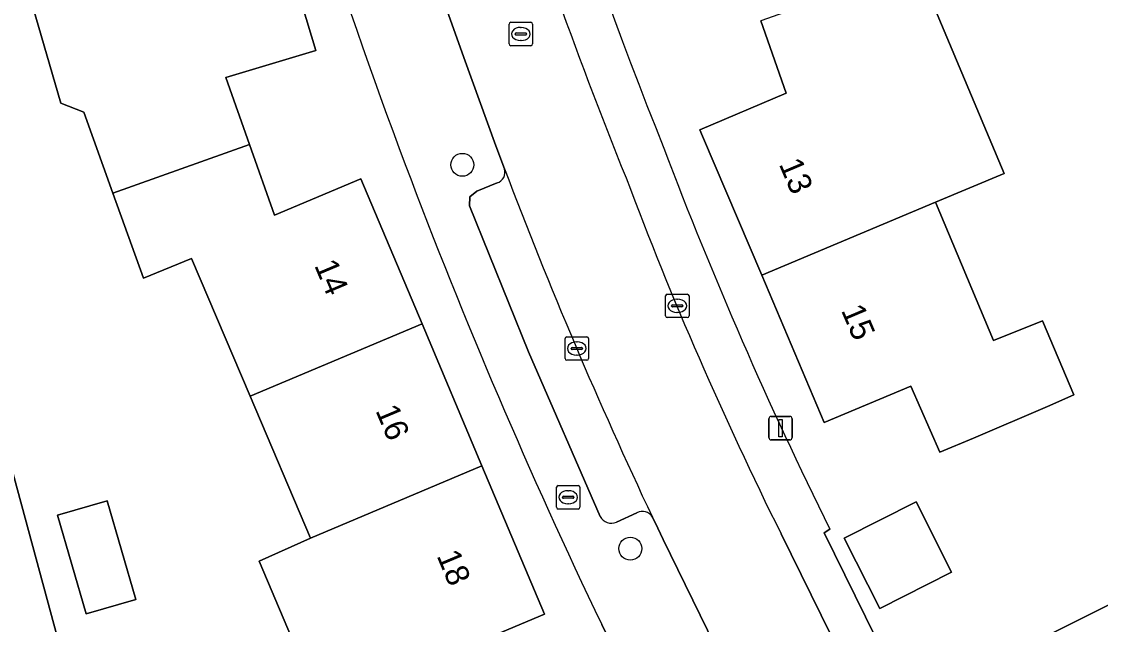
# Model space of a CAD drawing. Extents: x 159053 to 160042, y 380449 to 381423.
# Drawn here: x 159407.8 to 159453.83, y 380893.4 to 380919.13 of the extents above; entities that cross this region are included whole.
import ezdxf

# ---------------------------------------------------------------- set-up
doc = ezdxf.new("R2010")
doc.units = 0
for name, color, linetype in [('IMGEO_Boom', 7, 'Continuous'), ('IMGEO_Brandkraan', 7, 'Continuous'), ('IMGEO_Erf', 7, 'Continuous'), ('IMGEO_Groenvoorziening', 7, 'Continuous'), ('IMGEO_Kolk', 7, 'Continuous'), ('IMGEO_Lichtmast', 7, 'Continuous'), ('IMGEO_Pand', 7, 'Continuous'), ('IMGEO_Pand_nummerreeks', 7, 'Continuous'), ('IMGEO_Parkeervlak_open', 7, 'Continuous'), ('IMGEO_Rijbaan_lokaal_open', 7, 'Continuous'), ('IMGEO_Rioolput', 7, 'Continuous'), ('IMGEO_Voetpad_open', 7, 'Continuous')]:
    doc.layers.add(name, color=color, linetype=linetype)

msp = doc.modelspace()

# ---------------------------------------------------------------- linework, layer by layer
at = {"layer": 'IMGEO_Boom'}
for centre in [(159426.603, 380913.013), (159433.772, 380896.633)]:
    msp.add_circle(centre, 0.489, dxfattribs=at)
at = {"layer": 'IMGEO_Brandkraan'}
for p, q in [((159430.62, 380898.397), (159430.62, 380899.249)), ((159430.695, 380899.323), (159431.547, 380899.323)), ((159431.621, 380899.249), (159431.621, 380898.397)), ((159430.879, 380898.817), (159430.879, 380898.829)), ((159431.317, 380898.78), (159430.919, 380898.78)), ((159430.922, 380898.866), (159431.32, 380898.866)), ((159431.108, 380899.103), (159431.133, 380899.103)), ((159431.363, 380898.829), (159431.363, 380898.817)), ((159431.547, 380898.323), (159430.695, 380898.323)), ((159431.131, 380898.543), (159431.106, 380898.543))]:
    msp.add_line(p, q, dxfattribs=at)
for points in [[(159430.62, 380898.397), (159430.62, 380899.249)], [(159430.695, 380899.323), (159431.547, 380899.323)], [(159431.621, 380899.249), (159431.621, 380898.397)], [(159431.547, 380898.323), (159430.695, 380898.323)]]:
    msp.add_lwpolyline(points, dxfattribs=at)
for centre, radius, start, end in [((159430.697, 380899.247), 0.0765, 91.552, 178.448), ((159430.697, 380899.247), 0.0765, 91.552, 178.448), ((159431.545, 380899.247), 0.0765, 1.552, 88.448), ((159431.545, 380899.247), 0.0765, 1.552, 88.448), ((159430.919, 380898.826), 0.0403, 85.8775, 175.7526), ((159430.916, 380898.816), 0.0366, 178.938, 274.7102), ((159431.32, 380898.823), 0.043, 264.8664, 352.4533), ((159431.324, 380898.828), 0.0386, 1.7309, 96.639), ((159430.697, 380898.399), 0.0765, 181.552, 268.448), ((159430.697, 380898.399), 0.0765, 181.552, 268.448), ((159431.545, 380898.399), 0.0765, 271.552, 358.448), ((159431.545, 380898.399), 0.0765, 271.552, 358.448)]:
    msp.add_arc(centre, radius, start, end, dxfattribs=at)
for centre, major_axis, ratio, start_param, end_param in [((159431.107, 380898.823), (-0.387, 0.002), 0.722429, 4.712389, 7.853982), ((159431.132, 380898.823), (-0.39, 0.002), 0.717154, 1.570796, 4.712389)]:
    msp.add_ellipse(centre, major_axis=major_axis, ratio=ratio, start_param=start_param, end_param=end_param, dxfattribs=at)
at = {"layer": 'IMGEO_Erf'}
for points in [[(159408.965, 380964.525), (159406.59, 380964.068), (159401.237, 380962.888), (159388.835, 380959.508), (159387.783, 380959.221), (159399.303, 380929.877), (159412.172, 380882.306), (159415.898, 380867.448), (159416.608, 380864.597), (159416.656, 380864.403), (159417.452, 380863.784), (159418.791, 380864.086), (159429.053, 380866.431)], [(159418.369, 380924.458), (159420.347, 380917.887), (159416.517, 380916.735), (159417.526, 380913.88), (159418.591, 380910.865), (159422.277, 380912.418), (159424.886, 380906.225), (159427.441, 380900.163), (159430.109, 380893.831), (159426.433, 380892.288), (159427.633, 380889.421), (159427.088, 380889.202), (159422.993, 380887.56), (159421.762, 380887.066), (159417.932, 380896.096), (159420.125, 380897.081), (159417.551, 380903.138), (159415.055, 380909.013), (159413.002, 380908.175), (159411.697, 380911.8), (159410.451, 380915.26), (159409.474, 380915.644), (159407.916, 380920.993)], [(159445.993, 380921.527), (159449.718, 380912.643), (159446.793, 380911.415), (159449.265, 380905.517), (159451.363, 380906.349), (159452.697, 380903.191), (159451.578, 380902.697), (159448.411, 380901.353), (159446.975, 380900.743), (159445.736, 380903.567), (159442.047, 380902.022), (159439.379, 380908.299), (159436.855, 380914.238), (159436.742, 380914.504), (159440.424, 380916.069), (159439.335, 380919.157)], [(159452.048, 380890.082), (159450.799, 380892.535), (159457.704, 380896), (159468.395, 380899.243), (159469.193, 380896.611), (159480.383, 380897.975), (159480.699, 380888.61)], [(159442.282, 380897.463), (159442.043, 380897.312), (159451.283, 380878.508)], [(159442.437, 380873.196), (159432.55, 380893.397)]]:
    msp.add_lwpolyline(points, dxfattribs=at)
for points in [[(159411.451, 380898.672), (159412.675, 380894.468), (159410.558, 380893.852), (159409.334, 380898.055)], [(159447.479, 380895.625), (159444.416, 380894.078), (159442.9, 380897.079), (159445.963, 380898.626)]]:
    msp.add_lwpolyline(points, close=True, dxfattribs=at)
for centre, radius, start, end in [((159643.326, 380995.404), 234.129, 188.67315, 200.59863), ((159624.348, 380989.377), 203.718, 192.99702, 201.80088), ((159607.884, 380979.275), 184.709, 200.78794, 206.29061), ((159654.06, 380999.595), 245.652, 200.63276, 205.61432)]:
    msp.add_arc(centre, radius, start, end, dxfattribs=at)
at = {"layer": 'IMGEO_Groenvoorziening'}
msp.add_lwpolyline([(159339.63, 380858.444), (159343.386, 380845.223), (159357.481, 380849.075), (159416.608, 380864.597), (159415.898, 380867.448), (159412.172, 380882.306), (159399.303, 380929.877)], dxfattribs=at)
at = {"layer": 'IMGEO_Kolk'}
for p, q in [((159435.349, 380907.493), (159436.201, 380907.493)), ((159435.274, 380906.567), (159435.274, 380907.419)), ((159435.533, 380906.987), (159435.533, 380906.999)), ((159435.576, 380907.036), (159435.974, 380907.036)), ((159435.762, 380907.273), (159435.787, 380907.273)), ((159436.017, 380906.999), (159436.017, 380906.987)), ((159436.275, 380907.419), (159436.275, 380906.567)), ((159435.971, 380906.95), (159435.573, 380906.95)), ((159435.785, 380906.713), (159435.76, 380906.713)), ((159436.201, 380906.493), (159435.349, 380906.493)), ((159431.063, 380905.672), (159431.915, 380905.672)), ((159430.988, 380904.746), (159430.988, 380905.598)), ((159431.247, 380905.166), (159431.247, 380905.178)), ((159431.29, 380905.215), (159431.688, 380905.215)), ((159431.476, 380905.452), (159431.501, 380905.452)), ((159431.731, 380905.178), (159431.731, 380905.166)), ((159431.989, 380905.598), (159431.989, 380904.746)), ((159431.685, 380905.129), (159431.287, 380905.129)), ((159431.499, 380904.892), (159431.474, 380904.892)), ((159431.915, 380904.672), (159431.063, 380904.672))]:
    msp.add_line(p, q, dxfattribs=at)
for points in [[(159435.349, 380907.493), (159436.201, 380907.493)], [(159435.274, 380906.567), (159435.274, 380907.419)], [(159436.275, 380907.419), (159436.275, 380906.567)], [(159436.201, 380906.493), (159435.349, 380906.493)], [(159431.063, 380905.672), (159431.915, 380905.672)], [(159430.988, 380904.746), (159430.988, 380905.598)], [(159431.989, 380905.598), (159431.989, 380904.746)], [(159431.915, 380904.672), (159431.063, 380904.672)]]:
    msp.add_lwpolyline(points, dxfattribs=at)
for centre, radius, start, end in [((159435.351, 380907.417), 0.0765, 91.552, 178.448), ((159435.351, 380907.417), 0.0765, 91.552, 178.448), ((159436.199, 380907.417), 0.0765, 1.552, 88.448), ((159436.199, 380907.417), 0.0765, 1.552, 88.448), ((159435.573, 380906.996), 0.0403, 85.8775, 175.7526), ((159435.57, 380906.986), 0.0366, 178.938, 274.7102), ((159435.974, 380906.993), 0.043, 264.8664, 352.4533), ((159435.978, 380906.998), 0.0386, 1.7309, 96.639), ((159435.351, 380906.569), 0.0765, 181.552, 268.448), ((159435.351, 380906.569), 0.0765, 181.552, 268.448), ((159436.199, 380906.569), 0.0765, 271.552, 358.448), ((159436.199, 380906.569), 0.0765, 271.552, 358.448), ((159431.065, 380905.596), 0.0765, 91.552, 178.448), ((159431.065, 380905.596), 0.0765, 91.552, 178.448), ((159431.913, 380905.596), 0.0765, 1.552, 88.448), ((159431.913, 380905.596), 0.0765, 1.552, 88.448), ((159431.287, 380905.175), 0.0403, 85.8775, 175.7526), ((159431.284, 380905.165), 0.0366, 178.938, 274.7102), ((159431.688, 380905.172), 0.043, 264.8664, 352.4533), ((159431.692, 380905.177), 0.0386, 1.7309, 96.639), ((159431.065, 380904.748), 0.0765, 181.552, 268.448), ((159431.065, 380904.748), 0.0765, 181.552, 268.448), ((159431.913, 380904.748), 0.0765, 271.552, 358.448), ((159431.913, 380904.748), 0.0765, 271.552, 358.448)]:
    msp.add_arc(centre, radius, start, end, dxfattribs=at)
for centre, major_axis, ratio, start_param, end_param in [((159435.761, 380906.993), (-0.387, 0.002), 0.722429, 4.712389, 7.853982), ((159435.786, 380906.993), (-0.39, 0.002), 0.717154, 1.570796, 4.712389), ((159431.475, 380905.172), (-0.387, 0.002), 0.722429, 4.712389, 7.853982), ((159431.5, 380905.172), (-0.39, 0.002), 0.717154, 1.570796, 4.712389)]:
    msp.add_ellipse(centre, major_axis=major_axis, ratio=ratio, start_param=start_param, end_param=end_param, dxfattribs=at)
at = {"layer": 'IMGEO_Lichtmast'}
for p, q in [((159439.682, 380901.374), (159439.682, 380902.174)), ((159439.682, 380902.174), (159439.682, 380901.374)), ((159439.782, 380902.274), (159440.572, 380902.274)), ((159440.572, 380902.274), (159439.782, 380902.274)), ((159440.672, 380902.174), (159440.672, 380901.374)), ((159440.672, 380901.374), (159440.672, 380902.174)), ((159440.572, 380901.274), (159439.782, 380901.274)), ((159439.782, 380901.274), (159440.572, 380901.274))]:
    msp.add_line(p, q, dxfattribs=at)
msp.add_lwpolyline([(159440.102, 380902.149), (159440.252, 380902.149), (159440.252, 380901.399), (159440.102, 380901.399), (159440.102, 380902.149)], dxfattribs=at)
for centre, start, end in [((159439.782, 380902.174), 90, 180), ((159439.782, 380902.174), 90, 180), ((159440.572, 380902.174), 0, 90), ((159440.572, 380902.174), 360, 90), ((159439.782, 380901.374), 180, 270), ((159439.782, 380901.374), 180, 270), ((159440.572, 380901.374), 270, 0), ((159440.572, 380901.374), 270, 0)]:
    msp.add_arc(centre, 0.1, start, end, dxfattribs=at)
at = {"layer": 'IMGEO_Pand'}
for points in [[(159418.369, 380924.458), (159410.696, 380922.171), (159410.751, 380921.987), (159407.916, 380920.993), (159409.474, 380915.644), (159410.451, 380915.26), (159411.697, 380911.8), (159417.526, 380913.88), (159416.517, 380916.735), (159420.347, 380917.887)], [(159439.379, 380908.299), (159446.793, 380911.415), (159449.718, 380912.643), (159445.993, 380921.527), (159445.222, 380921.253), (159439.335, 380919.157), (159440.424, 380916.069), (159436.742, 380914.504), (159436.855, 380914.238)], [(159417.526, 380913.88), (159411.697, 380911.8), (159413.002, 380908.175), (159415.055, 380909.013), (159417.551, 380903.138), (159424.886, 380906.225), (159422.277, 380912.418), (159418.591, 380910.865)], [(159439.379, 380908.299), (159442.047, 380902.022), (159445.736, 380903.567), (159446.975, 380900.743), (159448.411, 380901.353), (159451.578, 380902.697), (159452.697, 380903.191), (159451.363, 380906.349), (159449.265, 380905.517), (159446.793, 380911.415)], [(159420.125, 380897.081), (159427.441, 380900.163), (159424.886, 380906.225), (159417.551, 380903.138)], [(159420.125, 380897.081), (159417.932, 380896.096), (159421.762, 380887.066), (159422.993, 380887.56), (159427.088, 380889.202), (159427.633, 380889.421), (159426.433, 380892.288), (159430.109, 380893.831), (159427.441, 380900.163)], [(159411.451, 380898.672), (159409.334, 380898.055), (159410.558, 380893.852), (159412.675, 380894.468)], [(159444.416, 380894.078), (159447.479, 380895.625), (159445.963, 380898.626), (159442.9, 380897.079)]]:
    msp.add_lwpolyline(points, close=True, dxfattribs=at)
msp.add_lwpolyline([(159462.103, 380884.706), (159458.502, 380893.368), (159457.704, 380896), (159450.799, 380892.535), (159452.048, 380890.082), (159448.483, 380888.267), (159451.307, 380883.741), (159451.847, 380882.876), (159455.107, 380884.541), (159455.564, 380883.052)], dxfattribs=at)
at = {"layer": 'IMGEO_Parkeervlak_open'}
for points in [[(159428.084, 380912.239), (159427.22, 380911.895), (159426.92, 380911.65), (159426.906, 380911.269), (159429.428, 380905.026), (159432.485, 380898.002)], [(159433.18, 380897.765), (159434.051, 380898.164)]]:
    msp.add_lwpolyline(points, dxfattribs=at)
for centre, radius, start, end in [((159427.936, 380912.705), 0.489, 287.6372, 16.4639), ((159618.579, 380984.756), 203.316, 200.71342, 205.2654), ((159432.963, 380898.266), 0.546, 208.8844, 293.4562), ((159434.283, 380897.719), 0.501, 31.0684, 117.4992)]:
    msp.add_arc(centre, radius, start, end, dxfattribs=at)
at = {"layer": 'IMGEO_Rijbaan_lokaal_open'}
for points in [[(159427.732, 380928.985), (159423.308, 380927.58), (159425.318, 380921.388), (159425.651, 380920.437), (159426.667, 380917.593), (159428.036, 380913.828), (159428.405, 380912.844)], [(159434.712, 380897.978), (159434.938, 380897.5), (159435.166, 380897.023), (159437.382, 380892.506), (159437.83, 380891.578), (159443.686, 380879.608), (159444.135, 380878.69), (159444.514, 380877.895), (159448.706, 380879.957), (159440.203, 380897.267)]]:
    msp.add_lwpolyline(points, dxfattribs=at)
for centre, radius, start, end in [((159625.145, 380989.617), 206.514, 197.07339, 201.94113), ((159618.579, 380984.756), 203.316, 200.71342, 205.2654), ((159585.371, 380969.529), 162.159, 200.60872, 206.46344)]:
    msp.add_arc(centre, radius, start, end, dxfattribs=at)
at = {"layer": 'IMGEO_Rioolput'}
for p, q in [((159428.6, 380918.171), (159428.6, 380919.023)), ((159428.675, 380919.097), (159429.527, 380919.097)), ((159429.601, 380919.023), (159429.601, 380918.171)), ((159428.859, 380918.591), (159428.859, 380918.603)), ((159429.297, 380918.554), (159428.899, 380918.554)), ((159428.902, 380918.64), (159429.3, 380918.64)), ((159429.088, 380918.877), (159429.113, 380918.877)), ((159429.343, 380918.603), (159429.343, 380918.591)), ((159429.527, 380918.097), (159428.675, 380918.097)), ((159429.111, 380918.317), (159429.086, 380918.317))]:
    msp.add_line(p, q, dxfattribs=at)
for points in [[(159428.6, 380918.171), (159428.6, 380919.023)], [(159428.675, 380919.097), (159429.527, 380919.097)], [(159429.601, 380919.023), (159429.601, 380918.171)], [(159429.527, 380918.097), (159428.675, 380918.097)]]:
    msp.add_lwpolyline(points, dxfattribs=at)
for centre, radius, start, end in [((159428.677, 380919.021), 0.0765, 91.552, 178.448), ((159428.677, 380919.021), 0.0765, 91.552, 178.448), ((159429.525, 380919.021), 0.0765, 1.552, 88.448), ((159429.525, 380919.021), 0.0765, 1.552, 88.448), ((159428.899, 380918.6), 0.0403, 85.8775, 175.7526), ((159428.896, 380918.59), 0.0366, 178.938, 274.7102), ((159429.3, 380918.597), 0.043, 264.8664, 352.4533), ((159429.304, 380918.602), 0.0386, 1.7309, 96.639), ((159428.677, 380918.173), 0.0765, 181.552, 268.448), ((159428.677, 380918.173), 0.0765, 181.552, 268.448), ((159429.525, 380918.173), 0.0765, 271.552, 358.448), ((159429.525, 380918.173), 0.0765, 271.552, 358.448)]:
    msp.add_arc(centre, radius, start, end, dxfattribs=at)
for centre, major_axis, ratio, start_param, end_param in [((159429.087, 380918.597), (-0.387, 0.002), 0.722429, 4.712389, 7.853982), ((159429.112, 380918.597), (-0.39, 0.002), 0.717154, 1.570796, 4.712389)]:
    msp.add_ellipse(centre, major_axis=major_axis, ratio=ratio, start_param=start_param, end_param=end_param, dxfattribs=at)
at = {"layer": 'IMGEO_Voetpad_open'}
for points in [[(159428.405, 380912.844), (159428.036, 380913.828), (159426.667, 380917.593), (159425.651, 380920.437), (159425.318, 380921.388)], [(159432.485, 380898.002), (159429.428, 380905.026), (159426.906, 380911.269), (159426.92, 380911.65), (159427.22, 380911.895), (159428.084, 380912.239)], [(159434.051, 380898.164), (159433.18, 380897.765)], [(159437.83, 380891.578), (159437.382, 380892.506), (159435.166, 380897.023), (159434.938, 380897.5), (159434.712, 380897.978)], [(159451.283, 380878.508), (159442.043, 380897.312), (159442.282, 380897.463)], [(159440.203, 380897.267), (159448.706, 380879.957), (159449.928, 380877.47)], [(159432.55, 380893.397), (159442.437, 380873.196)]]:
    msp.add_lwpolyline(points, dxfattribs=at)
for centre, radius, start, end in [((159643.326, 380995.404), 234.129, 188.67315, 200.59863), ((159624.348, 380989.377), 203.718, 192.99702, 201.80088), ((159625.145, 380989.617), 206.514, 197.07339, 201.94113), ((159607.884, 380979.275), 184.709, 200.78794, 206.29061), ((159654.06, 380999.595), 245.652, 200.63276, 205.61432), ((159427.936, 380912.705), 0.489, 287.6372, 16.4639), ((159585.371, 380969.529), 162.159, 200.60872, 206.46344), ((159432.963, 380898.266), 0.546, 208.8844, 293.4562), ((159434.283, 380897.719), 0.501, 31.0684, 117.4992)]:
    msp.add_arc(centre, radius, start, end, dxfattribs=at)

# ---------------------------------------------------------------- texts
at = {"layer": 'IMGEO_Pand_nummerreeks'}
for s, rotation, p in [('13', 293.0261, (159440.1, 380913.046)), ('14', 292.8491, (159420.275, 380908.725)), ('15', 293.0261, (159442.753, 380906.805)), ('16', 292.8491, (159422.886, 380902.529)), ('18', 292.8491, (159425.497, 380896.331))]:
    msp.add_text(s, height=1, rotation=rotation, dxfattribs=at).set_placement(p)

doc.saveas('drawing.dxf')
